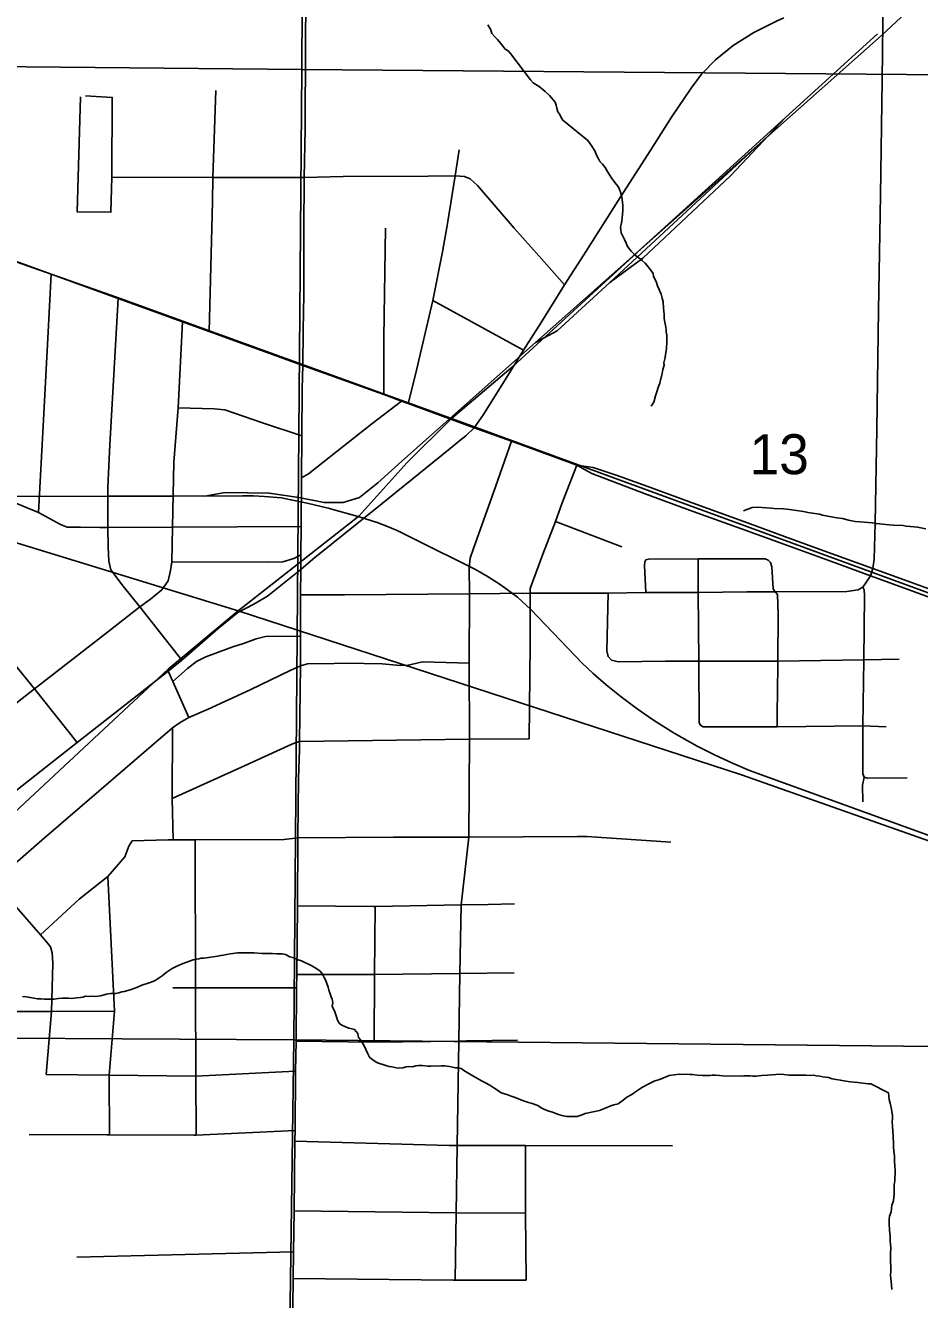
# Model space of a CAD drawing. Extents: x 0 to 34, y 0 to 22.
# Drawn here: x 7.229 to 8.166, y 17.171 to 18.505 of the extents above; entities that cross this region are included whole.
import ezdxf

# ---------------------------------------------------------------- set-up
doc = ezdxf.new("R2010")
doc.units = 0
for name, color, linetype in [('GM_X_City_Street', 7, 'Continuous'), ('GM_X_County_Road', 7, 'Continuous'), ('GM_X_Minor_River', 7, 'Continuous'), ('GM_X_Rail_Line', 7, 'Continuous'), ('GM_X_Section', 7, 'Continuous'), ('GM_X_Section_Text', 7, 'Continuous'), ('GM_X_State_Route', 7, 'Continuous'), ('GM_X_US_Route', 7, 'Continuous')]:
    doc.layers.add(name, color=color, linetype=linetype)

msp = doc.modelspace()

# ---------------------------------------------------------------- linework, layer by layer
at = {"layer": 'GM_X_City_Street'}
for p, q in [((7.6561, 18.2169), (7.7513, 18.165)), ((7.7846, 17.9856), (7.8542, 17.9592)), ((7.5175, 17.9088), (7.5568, 17.9089)), ((8.0168, 17.7705), (8.017, 17.7883)), ((7.714, 17.5846), (7.7417, 17.5851)), ((7.2833, 17.2152), (7.5103, 17.221)), ((7.6794, 17.1912), (7.7541, 17.1911))]:
    msp.add_line(p, q, dxfattribs=at)
for points in [[(8.1145, 17.9288), (8.1172, 17.9364), (8.1186, 17.9462), (8.1196, 17.9837), (8.1212, 18.0823), (8.1229, 18.2067), (8.1249, 18.3272), (8.1268, 18.4478), (8.1277, 18.5373), (8.1268, 18.5594)], [(7.4219, 18.1846), (7.4254, 18.3203), (7.4259, 18.3459), (7.4288, 18.437)], [(7.287, 18.4303), (7.2838, 18.3098), (7.3189, 18.3094), (7.3201, 18.346), (7.3203, 18.4296), (7.2923, 18.4314)], [(7.6712, 18.2957), (7.6719, 18.2996), (7.6797, 18.3475), (7.6839, 18.3747)], [(7.3201, 18.346), (7.4259, 18.3459), (7.5214, 18.3458), (7.5623, 18.3469), (7.6513, 18.3473), (7.6797, 18.3475), (7.6895, 18.347), (7.6952, 18.3445), (7.7031, 18.3374), (7.7415, 18.2929), (7.7674, 18.2634), (7.7941, 18.2334)], [(7.6049, 18.1185), (7.6049, 18.1783), (7.6067, 18.2928)], [(7.6305, 18.1091), (7.6375, 18.138), (7.6561, 18.2169), (7.6664, 18.2681), (7.6712, 18.2957)], [(7.2431, 17.995), (7.2484, 18.0919), (7.2528, 18.1774), (7.2563, 18.2446)], [(7.3933, 17.8405), (7.3492, 17.8963), (7.3317, 17.918), (7.3189, 17.9349), (7.3167, 17.9441), (7.3162, 17.9586), (7.3156, 17.9794), (7.3159, 18.0217), (7.3178, 18.0659), (7.3266, 18.219)], [(7.1768, 17.7617), (7.2391, 17.8103), (7.3155, 17.8696), (7.3492, 17.8963), (7.3603, 17.9043), (7.3723, 17.9142), (7.3788, 17.9234), (7.3815, 17.9344), (7.3828, 17.9435), (7.3835, 17.9797), (7.385, 18.0478), (7.3893, 18.1047), (7.3939, 18.1948)], [(7.3893, 18.1047), (7.4272, 18.1037), (7.4384, 18.1026), (7.4768, 18.0893), (7.5189, 18.0752)], [(7.5185, 18.0313), (7.5261, 18.0356), (7.5559, 18.0592), (7.5923, 18.0879), (7.6233, 18.1117)], [(7.6794, 17.1912), (7.6806, 17.2616), (7.6817, 17.3321), (7.6835, 17.4416), (7.6846, 17.5123), (7.6858, 17.5841), (7.6937, 17.6552), (7.6944, 17.7575), (7.6942, 17.8374), (7.6944, 17.9098), (7.6942, 17.9374), (7.6951, 17.9471), (7.699, 17.9583), (7.7196, 18.016), (7.7385, 18.0696)], [(7.7571, 17.758), (7.7582, 17.8567), (7.7581, 17.9104), (7.758, 17.9154), (7.7715, 17.9514), (7.7846, 17.9856), (7.7917, 18.0053), (7.7997, 18.0259), (7.807, 18.0446)], [(7.2836, 17.7541), (7.2391, 17.8103), (7.1354, 17.9374), (7.109, 17.9718), (7.1035, 17.9791), (7.0343, 17.9794), (6.9579, 17.9797), (6.9509, 17.9797)], [(7.3828, 17.9435), (7.4834, 17.9429), (7.4992, 17.9434), (7.5105, 17.9468), (7.518, 17.9506)], [(7.8793, 17.9111), (7.8779, 17.9395), (7.8782, 17.9435), (7.8791, 17.9454), (7.8821, 17.9462), (7.934, 17.9464), (7.9674, 17.9464), (8.0043, 17.9464), (8.0074, 17.945), (8.0098, 17.9428), (8.0114, 17.9381), (8.0127, 17.9151), (8.0147, 17.912)], [(7.9367, 17.7722), (7.9352, 17.7748), (7.9349, 17.8395), (7.9342, 17.9114), (7.934, 17.9464)], [(7.5568, 17.9089), (7.5637, 17.9089), (7.6944, 17.9098), (7.7581, 17.9104), (7.8399, 17.9107), (7.8793, 17.9111), (7.9342, 17.9114), (7.9851, 17.9118), (8.0147, 17.912), (8.0897, 17.9122), (8.1016, 17.9139), (8.1066, 17.9168), (8.1103, 17.9223), (8.1145, 17.9288)], [(8.1064, 17.692), (8.1062, 17.7096), (8.1081, 17.7179), (8.1064, 17.7212), (8.1066, 17.7715), (8.1076, 17.8406), (8.1083, 17.908), (8.108, 17.9139), (8.1066, 17.9168)], [(7.8434, 17.8403), (7.8398, 17.8442), (7.8385, 17.85), (7.8399, 17.9107)], [(8.017, 17.7883), (8.0171, 17.8044), (8.0174, 17.8395), (8.0179, 17.8886), (8.0173, 17.9092), (8.0147, 17.912)], [(7.3837, 17.8181), (7.3991, 17.8316), (7.4087, 17.8391), (7.4185, 17.8438), (7.4334, 17.8493), (7.4468, 17.8542), (7.458, 17.8579), (7.4712, 17.8627), (7.481, 17.865), (7.5174, 17.8654)], [(6.7594, 17.8514), (6.8445, 17.8503), (6.8714, 17.8506), (6.9553, 17.8489), (6.9869, 17.8427), (7.0017, 17.8385), (7.0187, 17.8302), (7.0332, 17.8134), (7.0648, 17.774), (7.0782, 17.7562), (7.1139, 17.7119), (7.1572, 17.6552), (7.1963, 17.6084), (7.2194, 17.5823), (7.2451, 17.5529), (7.2515, 17.5456), (7.2556, 17.5403), (7.2576, 17.5341), (7.2582, 17.523), (7.2569, 17.4725), (7.2511, 17.4066)], [(7.513, 17.8322), (7.5175, 17.8343), (7.5249, 17.8365), (7.5529, 17.837)], [(7.5529, 17.837), (7.5649, 17.8373), (7.603, 17.8366), (7.6181, 17.8352), (7.6291, 17.8348), (7.6454, 17.8386), (7.6942, 17.8374)], [(7.8434, 17.8403), (7.8504, 17.8387), (7.8998, 17.8393), (7.9349, 17.8395), (8.0174, 17.8395), (8.1076, 17.8406), (8.1446, 17.8414)], [(7.0405, 17.4732), (7.0472, 17.4797), (7.0785, 17.5066), (7.1258, 17.5472), (7.1555, 17.5732), (7.1743, 17.5898), (7.1963, 17.6084), (7.2467, 17.6518), (7.3835, 17.7695), (7.3914, 17.7751), (7.4006, 17.7802), (7.4207, 17.7892), (7.4647, 17.8093), (7.5075, 17.8298), (7.513, 17.8322)], [(7.4006, 17.7802), (7.3837, 17.8181), (7.3789, 17.8287)], [(7.3843, 17.6522), (7.3832, 17.6954), (7.3835, 17.7695)], [(7.9367, 17.7722), (7.9394, 17.7706), (8.0168, 17.7705), (8.1066, 17.7715), (8.1311, 17.7707)], [(7.3832, 17.6954), (7.4596, 17.7301), (7.5045, 17.7507), (7.5101, 17.7533), (7.5166, 17.7554), (7.6944, 17.7575), (7.7571, 17.758)], [(8.1081, 17.7179), (8.1114, 17.7169), (8.1529, 17.7173)], [(7.2451, 17.5529), (7.2859, 17.5903), (7.3158, 17.614), (7.3335, 17.6345), (7.3379, 17.6456), (7.3412, 17.6511), (7.3789, 17.6522), (7.3843, 17.6522), (7.4071, 17.6523), (7.5003, 17.6526), (7.5148, 17.6542), (7.615, 17.655), (7.6937, 17.6552), (7.8078, 17.6559)], [(7.4082, 17.343), (7.408, 17.4049), (7.4076, 17.4974), (7.4071, 17.6523)], [(7.8078, 17.6559), (7.8176, 17.6559), (7.9056, 17.6499)], [(7.3176, 17.3433), (7.3172, 17.4035), (7.3172, 17.4059), (7.3227, 17.4727), (7.3158, 17.614)], [(7.5145, 17.5833), (7.5941, 17.5825), (7.5959, 17.5826), (7.6679, 17.5838), (7.6858, 17.5841), (7.714, 17.5846)], [(7.5946, 17.4404), (7.5952, 17.5111), (7.5959, 17.5826)], [(7.5136, 17.5112), (7.5952, 17.5111), (7.6846, 17.5123), (7.7413, 17.5131)], [(7.3839, 17.4974), (7.4076, 17.4974), (7.5132, 17.4972)], [(7.0072, 17.472), (7.0405, 17.4732), (7.1522, 17.4725), (7.2569, 17.4725), (7.3227, 17.4727)], [(7.513, 17.4416), (7.5946, 17.4404), (7.6835, 17.4416), (7.6914, 17.4417), (7.745, 17.4424)], [(7.2511, 17.4066), (7.3172, 17.4059), (7.408, 17.4049), (7.5123, 17.4101)], [(7.2334, 17.3437), (7.3146, 17.3434), (7.3176, 17.3433), (7.406, 17.343), (7.4082, 17.343), (7.5119, 17.3479)], [(7.5116, 17.3367), (7.6733, 17.3321), (7.6817, 17.3321), (7.7533, 17.3323), (7.9071, 17.3318)], [(7.7541, 17.1911), (7.7533, 17.2615), (7.7533, 17.3323)], [(7.511, 17.2637), (7.6806, 17.2616), (7.7533, 17.2615)], [(7.51, 17.193), (7.6775, 17.1912), (7.6794, 17.1912)]]:
    msp.add_lwpolyline(points, dxfattribs=at)
at = {"layer": 'GM_X_County_Road'}
for points in [[(7.3075, 17.9794), (7.2872, 17.9796), (7.2731, 17.9796), (7.2661, 17.9826), (7.2431, 17.995), (7.2012, 18.012), (7.1726, 18.0219), (7.173, 18.0289)], [(7.5181, 17.9805), (7.3835, 17.9797), (7.3156, 17.9794), (7.3075, 17.9794)], [(7.1618, 17.6588), (7.1875, 17.6787), (7.246, 17.7246), (7.2836, 17.7541), (7.3286, 17.7895), (7.3789, 17.8287), (7.3933, 17.8405), (7.4314, 17.8737), (7.452, 17.8902), (7.4686, 17.899), (7.4829, 17.9074), (7.5178, 17.9352)]]:
    msp.add_lwpolyline(points, dxfattribs=at)
at = {"layer": 'GM_X_Minor_River'}
for points in [[(7.7139, 18.5057), (7.717, 18.5004), (7.7181, 18.4966), (7.7212, 18.4932), (7.7239, 18.4902), (7.7269, 18.4864), (7.73, 18.483), (7.7319, 18.4803), (7.7349, 18.4784), (7.7376, 18.4758), (7.7586, 18.4482), (7.7613, 18.4448), (7.7639, 18.4433), (7.7674, 18.441), (7.7738, 18.4357), (7.7784, 18.4316), (7.7842, 18.4248), (7.7853, 18.4217), (7.7861, 18.4183), (7.7872, 18.4145), (7.7892, 18.4119), (7.7903, 18.4092), (7.7922, 18.4058), (7.8185, 18.3847), (7.8204, 18.382), (7.8227, 18.3786), (7.8258, 18.3737), (7.8281, 18.3684), (7.8296, 18.3653), (7.8311, 18.3627), (7.8338, 18.3597), (7.8365, 18.3563), (7.8396, 18.3513), (7.8419, 18.3475), (7.8438, 18.3449), (7.8483, 18.3388), (7.8503, 18.3362), (7.8518, 18.3332), (7.8529, 18.3305), (7.8541, 18.3252), (7.8549, 18.3199), (7.8553, 18.3168), (7.8553, 18.3115), (7.855, 18.307), (7.8542, 18.3001), (7.8535, 18.2967), (7.8527, 18.2937), (7.8531, 18.2906), (7.8535, 18.288), (7.857, 18.2808), (7.8585, 18.277), (7.8601, 18.2736), (7.8639, 18.2686), (7.8685, 18.2641), (7.8719, 18.2618), (7.8753, 18.2588), (7.8784, 18.2562), (7.8818, 18.2524), (7.8841, 18.249), (7.8868, 18.2452), (7.8872, 18.2426), (7.8887, 18.2395), (7.8902, 18.2369), (7.8914, 18.2323), (7.8929, 18.2293), (7.8941, 18.2266), (7.8952, 18.2236), (7.8964, 18.2194), (7.8975, 18.2156), (7.8976, 18.2088), (7.8984, 18.2027), (7.8984, 18.1982)], [(7.8984, 18.1982), (7.8992, 18.1944), (7.9003, 18.1891), (7.9007, 18.1864), (7.9007, 18.1837), (7.9011, 18.1807), (7.9012, 18.1716), (7.9008, 18.1689), (7.9008, 18.1663), (7.8997, 18.1606), (7.8994, 18.1572), (7.8982, 18.1518), (7.8983, 18.1492), (7.8971, 18.1446), (7.8964, 18.1404), (7.8957, 18.1374), (7.8945, 18.134), (7.8938, 18.1305), (7.8927, 18.1271), (7.8904, 18.1203), (7.8893, 18.1172), (7.8878, 18.1104), (7.8848, 18.1062)], [(7.9814, 17.9969), (7.9905, 18.0003), (7.9962, 18.0007), (8.0011, 18.0004), (8.0102, 17.9997), (8.0136, 17.9993), (8.0235, 17.999), (8.0269, 17.9986), (8.0296, 17.9982), (8.0421, 17.9964), (8.0463, 17.9957), (8.049, 17.9949), (8.0611, 17.9931), (8.0642, 17.9923), (8.0756, 17.9901), (8.0794, 17.9894), (8.0851, 17.9886), (8.0915, 17.9871), (8.0984, 17.9857), (8.1033, 17.9853), (8.1166, 17.9842), (8.1204, 17.9835), (8.1341, 17.982), (8.1386, 17.9817), (8.1489, 17.9813), (8.1519, 17.9806), (8.1603, 17.9799), (8.1637, 17.9795), (8.1724, 17.978)], [(7.2263, 17.4882), (7.2301, 17.4878), (7.2343, 17.487), (7.2384, 17.4866), (7.2422, 17.4858), (7.246, 17.4857), (7.249, 17.4853), (7.2566, 17.4853), (7.2597, 17.4856), (7.2642, 17.486), (7.2684, 17.4863), (7.2745, 17.4863), (7.2782, 17.4862), (7.2828, 17.4869), (7.287, 17.4873), (7.2896, 17.4876), (7.2923, 17.4884), (7.2957, 17.4883), (7.2987, 17.4887), (7.3014, 17.4883), (7.3052, 17.4886), (7.3079, 17.489), (7.3105, 17.4897), (7.3143, 17.4905), (7.3185, 17.4912), (7.3238, 17.4915), (7.3272, 17.4922), (7.3303, 17.493), (7.3329, 17.4933), (7.3367, 17.4944), (7.3401, 17.4955), (7.347, 17.4981), (7.3512, 17.5), (7.358, 17.5022), (7.3611, 17.5033), (7.3653, 17.5048), (7.3694, 17.5078), (7.3725, 17.5097), (7.3767, 17.5134), (7.3832, 17.5176), (7.3874, 17.5198), (7.3935, 17.5224), (7.3976, 17.5239), (7.4022, 17.5254), (7.4053, 17.5265), (7.4109, 17.5276), (7.4136, 17.5283), (7.4163, 17.5283), (7.4189, 17.5286), (7.4235, 17.5294), (7.4261, 17.5297), (7.4307, 17.5304), (7.4341, 17.5312), (7.4372, 17.5315), (7.4402, 17.5322), (7.444, 17.533), (7.4466, 17.5333), (7.4516, 17.534), (7.469, 17.5339), (7.477, 17.5334), (7.4884, 17.5333), (7.4929, 17.5329), (7.4982, 17.5329), (7.502, 17.5321), (7.5065, 17.5298), (7.5107, 17.5286), (7.5152, 17.5266), (7.5186, 17.5255), (7.522, 17.5239), (7.5251, 17.5224), (7.5288, 17.5208), (7.5319, 17.5189), (7.5356, 17.5166), (7.5383, 17.5147), (7.5405, 17.5116), (7.5424, 17.5082), (7.5439, 17.5055), (7.545, 17.5017), (7.5465, 17.4979), (7.5472, 17.4949), (7.5483, 17.4922), (7.5498, 17.488), (7.5509, 17.4853), (7.5513, 17.4815), (7.5509, 17.4781)], [(7.5509, 17.4781), (7.5535, 17.472), (7.5553, 17.4671), (7.5564, 17.4636), (7.5583, 17.4598), (7.5609, 17.4583), (7.5639, 17.4567), (7.5681, 17.4552), (7.5715, 17.4544), (7.5742, 17.4536), (7.5775, 17.4494), (7.5783, 17.4452), (7.5809, 17.4425), (7.5843, 17.4364), (7.5861, 17.4326), (7.588, 17.4281), (7.5898, 17.4246), (7.5936, 17.4215), (7.5974, 17.4192), (7.6004, 17.4181), (7.6038, 17.4169), (7.608, 17.4157), (7.6106, 17.4149), (7.6133, 17.4145), (7.6182, 17.4137), (7.6212, 17.4133), (7.6246, 17.4137), (7.6284, 17.4144), (7.6322, 17.4148), (7.6349, 17.4147), (7.6383, 17.4155), (7.641, 17.4158), (7.6451, 17.4158), (7.6508, 17.4153), (7.6542, 17.4153), (7.6649, 17.4156), (7.6686, 17.4156), (7.6736, 17.4148), (7.68, 17.4136), (7.6827, 17.4135), (7.6857, 17.4128), (7.6887, 17.4108), (7.6921, 17.4085), (7.6981, 17.4051), (7.7072, 17.4), (7.7114, 17.3977), (7.7159, 17.3954), (7.72, 17.3927), (7.7227, 17.3908), (7.7279, 17.3873), (7.7348, 17.3854), (7.7382, 17.3838), (7.7423, 17.3823), (7.7484, 17.3799), (7.751, 17.3788), (7.7563, 17.3772), (7.7593, 17.3764), (7.7661, 17.3741), (7.7695, 17.3718), (7.7733, 17.3698), (7.7775, 17.3683), (7.7816, 17.3671), (7.7877, 17.3648), (7.7926, 17.3632), (7.7968, 17.3624), (7.8074, 17.3627), (7.8116, 17.3638), (7.8158, 17.3657), (7.8306, 17.369), (7.8359, 17.3708), (7.8427, 17.3738), (7.8458, 17.3749), (7.8503, 17.376), (7.8557, 17.3797), (7.8595, 17.3828), (7.8645, 17.3857), (7.8683, 17.3884), (7.8759, 17.3932), (7.8824, 17.3966), (7.8881, 17.3996), (7.8946, 17.4018), (7.9037, 17.4055), (7.9143, 17.4069), (7.917, 17.4065), (7.92, 17.4069), (7.9257, 17.4065), (7.9283, 17.4064), (7.9333, 17.406), (7.9386, 17.4056), (7.9462, 17.4055), (7.9488, 17.4059), (7.9522, 17.4059), (7.9564, 17.4054), (7.9598, 17.405), (7.978, 17.4049), (7.9818, 17.4052), (7.986, 17.4052), (7.9886, 17.4051), (7.9913, 17.4047), (7.9947, 17.4047), (8.0004, 17.4054)], [(8.0004, 17.4054), (8.0068, 17.4057), (8.011, 17.4061), (8.0201, 17.4068), (8.0239, 17.4067), (8.0292, 17.4059), (8.0467, 17.4058), (8.0516, 17.4054), (8.055, 17.4057), (8.0577, 17.4053), (8.0614, 17.4049), (8.0648, 17.4041), (8.0675, 17.4037), (8.0705, 17.4033), (8.0743, 17.4021), (8.0785, 17.4013), (8.083, 17.4005), (8.0887, 17.3997), (8.0936, 17.3989), (8.1012, 17.3981), (8.1039, 17.3977), (8.1122, 17.3968), (8.1148, 17.3968), (8.1334, 17.3875), (8.1341, 17.3803), (8.1352, 17.3765), (8.1366, 17.3701), (8.137, 17.3674), (8.1377, 17.364), (8.1377, 17.3606), (8.1373, 17.3571), (8.1376, 17.3522), (8.1379, 17.3476), (8.1383, 17.3416), (8.1386, 17.3343), (8.1386, 17.3313), (8.1389, 17.326), (8.1396, 17.3214), (8.1396, 17.3157), (8.1403, 17.3059), (8.1402, 17.2952), (8.1394, 17.2911), (8.1393, 17.2816), (8.1388, 17.2744), (8.1369, 17.2698), (8.1365, 17.266), (8.1361, 17.2626), (8.1345, 17.2581), (8.1341, 17.2547), (8.1341, 17.2501), (8.1344, 17.244), (8.1351, 17.2364), (8.1351, 17.2319), (8.1354, 17.2288), (8.1358, 17.2246), (8.1357, 17.2193), (8.1357, 17.2098), (8.136, 17.206), (8.136, 17.2011), (8.1355, 17.1962), (8.1362, 17.1897), (8.1366, 17.1859), (8.1369, 17.1814)]]:
    msp.add_lwpolyline(points, dxfattribs=at)
at = {"layer": 'GM_X_Rail_Line'}
for p, q in [((8.0252, 18.4083), (8.1219, 18.4962)), ((8.0078, 18.3896), (8.0252, 18.4083)), ((7.8414, 18.2359), (8.0078, 18.3896)), ((7.4524, 17.8921), (7.5787, 17.9911))]:
    msp.add_line(p, q, dxfattribs=at)
for points in [[(2.1, 20.1355), (2.5574, 19.9667), (3.1422, 19.7506), (3.6996, 19.5506), (4.3507, 19.3207), (4.9212, 19.1118), (5.8157, 18.7674), (6.212, 18.6139), (6.6644, 18.4531), (7.3247, 18.2205), (7.6757, 18.0934)], [(2.1, 19.5186), (2.8346, 19.2964), (3.6748, 19.0394), (4.5141, 18.7823), (5.7652, 18.3991), (6.2109, 18.2673), (6.7654, 18.1025), (7.4524, 17.8921)], [(7.6757, 18.0934), (7.7402, 18.1481), (7.8743, 18.2711), (8.1262, 18.4945), (8.4641, 18.8097), (8.6445, 18.9615), (8.7545, 19.0553), (8.9, 19.1876)], [(7.7637, 18.173), (7.8685, 18.2658), (8.0252, 18.4083)], [(7.8414, 18.2359), (7.876, 18.2614), (7.968, 18.3476), (8.0078, 18.3896)], [(7.7637, 18.173), (7.7865, 18.1852), (7.8414, 18.2359)], [(7.4172, 18.0122), (7.4388, 18.016), (7.4849, 18.0154), (7.5158, 18.0106), (7.5424, 18.0056), (7.5622, 18.0055), (7.5792, 18.0106), (7.5985, 18.0262), (7.6237, 18.0489), (7.7637, 18.173)], [(7.5787, 17.9911), (7.6288, 18.0471), (7.6757, 18.0934)], [(7.6757, 18.0934), (8.5713, 17.7661), (8.9, 17.6476)], [(7.1662, 18.0122), (7.2447, 18.0118), (7.3158, 18.012), (7.3836, 18.0121), (7.4569, 18.0123), (7.4685, 18.0123), (7.4798, 18.0117), (7.4976, 18.0102), (7.5075, 18.0084), (7.5244, 18.0049), (7.5464, 17.9997), (7.5789, 17.9905), (7.5978, 17.9845), (7.6069, 17.9811), (7.6187, 17.9762), (7.6364, 17.9675), (7.701, 17.9354), (7.714, 17.9276), (7.7277, 17.9188), (7.745, 17.9065), (7.7589, 17.8934), (7.8127, 17.8373), (7.8242, 17.8266), (7.8378, 17.8147), (7.8536, 17.802), (7.8703, 17.7893), (7.8873, 17.7774), (7.9089, 17.7638), (7.9329, 17.7502), (7.9511, 17.7411), (7.97, 17.7324), (7.988, 17.7248), (8.2105, 17.6444)], [(3.6815, 14.4919), (3.8612, 14.6519), (4.1651, 14.9197), (4.4686, 15.1913), (4.7768, 15.471), (5.1412, 15.8006), (5.4601, 16.0872), (6.2018, 16.7592), (6.7493, 17.2493), (7.0065, 17.4955), (7.1712, 17.6375), (7.3789, 17.8309), (7.4524, 17.8921)], [(7.4524, 17.8921), (7.9795, 17.7204), (8.4514, 17.5539), (8.9, 17.3924)]]:
    msp.add_lwpolyline(points, dxfattribs=at)
at = {"layer": 'GM_X_Section'}
for points in [[(6.5246, 19.4487), (7.5241, 19.4466), (7.5189, 18.4589), (6.5078, 18.4687)], [(7.5241, 19.4466), (8.547, 19.4493), (8.532, 18.4506), (7.5189, 18.4589)], [(7.5189, 18.4589), (7.5107, 17.4428), (6.4919, 17.4489), (6.5078, 18.4687)], [(8.532, 18.4506), (8.5188, 17.4323), (7.5107, 17.4428), (7.5189, 18.4589)], [(6.4919, 17.4489), (7.5107, 17.4428), (7.4967, 16.4401), (6.481, 16.4419)], [(8.5188, 17.4323), (8.5041, 16.4364), (7.4967, 16.4401), (7.5107, 17.4428)]]:
    msp.add_lwpolyline(points, close=True, dxfattribs=at)
at = {"layer": 'GM_X_State_Route'}
for points in [[(7.5227, 18.4496), (7.5229, 18.4897), (7.5234, 18.5651), (7.5238, 18.6247), (7.5241, 18.6895), (7.5241, 18.6997)], [(7.6994, 18.0838), (7.7092, 18.0975), (7.7331, 18.1356), (7.7513, 18.165), (7.7697, 18.1938), (7.7941, 18.2334), (7.8142, 18.2647), (7.8523, 18.3248), (7.8844, 18.3749), (7.9062, 18.4091), (7.9269, 18.4394), (7.9375, 18.454), (7.9522, 18.4689), (7.9708, 18.4839), (7.9923, 18.4976), (8.0167, 18.5098), (8.0239, 18.5131)], [(7.5199, 18.149), (7.5202, 18.1855), (7.5209, 18.2237), (7.5211, 18.2907), (7.5214, 18.3458), (7.5223, 18.3967), (7.5225, 18.4316), (7.5227, 18.4496)], [(7.5178, 17.9352), (7.518, 17.9506), (7.5181, 17.9805), (7.5185, 18.0313), (7.5189, 18.0752), (7.5193, 18.1245), (7.5199, 18.149)], [(7.6846, 18.0703), (7.6909, 18.0754), (7.6994, 18.0838)], [(7.5178, 17.9352), (7.5304, 17.9462), (7.5501, 17.962), (7.6031, 18.0046), (7.6562, 18.0475), (7.6742, 18.062), (7.6846, 18.0703)], [(7.5164, 17.7464), (7.5166, 17.7554), (7.5175, 17.8343), (7.5174, 17.8654), (7.5175, 17.9088), (7.5178, 17.9352)], [(7.5116, 17.3377), (7.5119, 17.3479), (7.5123, 17.4101), (7.513, 17.4416), (7.5132, 17.4972), (7.5136, 17.5112), (7.5145, 17.5833), (7.5148, 17.6542), (7.5155, 17.7164), (7.5164, 17.7464)], [(7.4978, 16.5516), (7.4995, 16.5896), (7.5028, 16.737), (7.5058, 16.9041), (7.5078, 17.0349), (7.5097, 17.1641), (7.51, 17.193), (7.5103, 17.221), (7.511, 17.2637), (7.5116, 17.3367), (7.5116, 17.3377)]]:
    msp.add_lwpolyline(points, dxfattribs=at)
at = {"layer": 'GM_X_US_Route'}
for points in [[(6.7993, 18.4076), (6.8041, 18.4059), (6.8793, 18.3795), (6.9706, 18.3476), (7.0374, 18.3239), (7.1241, 18.2926), (7.1881, 18.2693), (7.2563, 18.2446), (7.3266, 18.219), (7.3939, 18.1948), (7.4219, 18.1846), (7.5199, 18.149)], [(7.5199, 18.149), (7.6049, 18.1185), (7.6233, 18.1117), (7.6305, 18.1091), (7.6994, 18.0838)], [(7.6994, 18.0838), (7.7385, 18.0696), (7.807, 18.0446), (7.8157, 18.0397)], [(7.807, 18.0446), (7.8242, 18.042), (7.8491, 18.0336), (7.8814, 18.0221), (7.9317, 18.0038), (7.982, 17.9856), (8.0312, 17.9676), (8.0784, 17.9505), (8.1172, 17.9364)], [(7.8157, 18.0397), (7.8226, 18.0358), (7.8787, 18.0145), (7.929, 17.9962), (7.9793, 17.978), (8.0286, 17.96), (8.0785, 17.9419), (8.1145, 17.9288), (8.1503, 17.9157), (8.2291, 17.8869), (8.3004, 17.8606), (8.3938, 17.8264), (8.4789, 17.7954), (8.5217, 17.7801), (8.5262, 17.7785), (8.6013, 17.7506), (8.7009, 17.7143), (8.7516, 17.6958)], [(8.1172, 17.9364), (8.1499, 17.9246), (8.2076, 17.9035), (8.2651, 17.8825), (8.3153, 17.864), (8.3797, 17.8405), (8.4295, 17.8221), (8.4801, 17.8037), (8.5074, 17.7937), (8.5218, 17.7883), (8.5272, 17.7863)]]:
    msp.add_lwpolyline(points, dxfattribs=at)

# ---------------------------------------------------------------- texts
at = {"layer": 'GM_X_Section_Text'}
msp.add_text('13', height=0.04186, rotation=0, dxfattribs=at).set_placement((7.9878, 18.0351))

doc.saveas('drawing.dxf')
